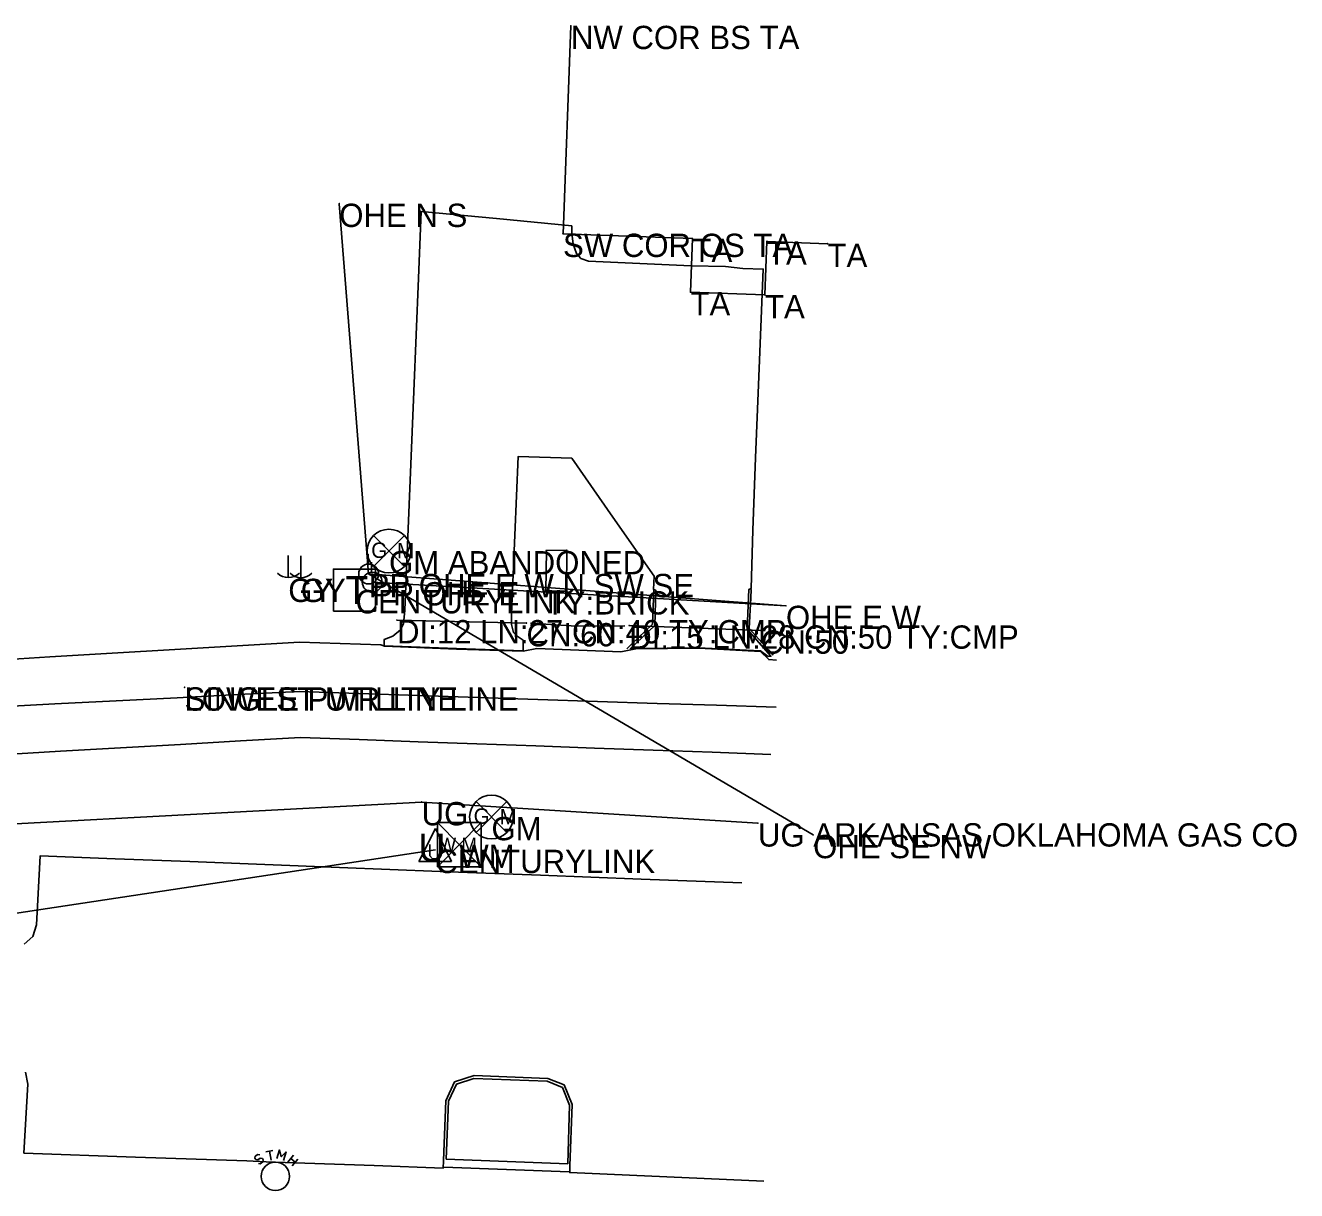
# Model space of a CAD drawing. Extents: x 675481 to 678499, y 212715 to 215285.
# Drawn here: x 678226 to 678498.8, y 214489.7 to 214739.6 of the extents above; entities that cross this region are included whole.
import ezdxf

# ---------------------------------------------------------------- set-up
doc = ezdxf.new("R2010")
doc.units = 0
for name, color, linetype in [('Default', 7, 'Continuous'), ('S_BUILDING', 7, 'Continuous'), ('S_BUILDING_ANNOT', 7, 'Continuous'), ('S_CURB', 7, 'Continuous'), ('S_DITCHLINE', 7, 'Continuous'), ('S_DRG_PT_SYM', 7, 'Continuous'), ('S_EDGE_CONCRETE', 7, 'Continuous'), ('S_EDGE_PAVEMENT', 7, 'Continuous'), ('S_ELECTRIC_UTILITIES', 7, 'Continuous'), ('S_ELECTRIC_UTILITIES_ANNOT', 7, 'Continuous'), ('S_GAS_UTILITIES', 7, 'Continuous'), ('S_GAS_UTILITIES_ANNOT', 7, 'Continuous'), ('S_MSC_PT_SYM', 7, 'Continuous'), ('S_PAVEMENT_CROWN', 7, 'Continuous'), ('S_SIDE_DRAIN', 7, 'Continuous'), ('S_SIDE_DRAIN_ANNOT', 7, 'Continuous'), ('S_SIGN', 7, 'Continuous'), ('S_SIGN_ANNOT', 7, 'Continuous'), ('S_STORM_SEWER', 7, 'Continuous'), ('S_STR_PT_SYM', 7, 'Continuous'), ('S_SURVEY_TEXT_ANNOT', 7, 'Continuous'), ('S_TELEPHONE_UTILITIES', 7, 'Continuous'), ('S_TELEPHONE_UTILITIES_ANNOT', 7, 'Continuous'), ('S_UNDERGROUND_CABLE', 7, 'Continuous'), ('S_UNDERGROUND_CABLE_ANNOT', 7, 'Continuous'), ('S_UTILITY_POLE', 7, 'Continuous'), ('S_UTILITY_POLE_ANNOT', 7, 'Continuous'), ('S_UTL_PT_SYM', 7, 'Continuous'), ('S_WATER_UTILITIES', 7, 'Continuous'), ('S_WATER_UTILITIES_ANNOT', 7, 'Continuous')]:
    doc.layers.add(name, color=color, linetype=linetype)

msp = doc.modelspace()

# ---------------------------------------------------------------- linework, layer by layer
at = {"layer": 'S_BUILDING'}
for p, q in [((678341.33, 214694.94), (678343.02, 214739.54)), ((678341.33, 214694.94), (678369.11, 214693.89)), ((678369.11, 214693.89), (678368.68, 214682.4)), ((678384.67, 214681.79), (678385.1, 214693.29)), ((678385.1, 214693.29), (678398.09, 214692.79)), ((678368.68, 214682.4), (678384.67, 214681.79))]:
    msp.add_line(p, q, dxfattribs=at)
at = {"layer": 'S_CURB'}
for points in [[(678360.8, 214618.48), (678360.76, 214616.66), (678360.54, 214611.15), (678355.96, 214606.79), (678355, 214605.85)], [(678386.45, 214604.54), (678385.42, 214605.68), (678381.3, 214610.21), (678381.6, 214616.83), (678381.71, 214618.6)], [(678342.35, 214495.43), (678329.31, 214495.92), (678316.26, 214496.41), (678316.76, 214508.83), (678318.49, 214512.5), (678322.22, 214513.73), (678337.92, 214513.14), (678341.2, 214511.79), (678342.75, 214507.99)], [(678342.75, 214507.99), (678342.35, 214495.43)], [(678315.73, 214494.67), (678329.2, 214494.18), (678342.67, 214493.7)]]:
    msp.add_lwpolyline(points, dxfattribs=at)
at = {"layer": 'S_DITCHLINE'}
msp.add_lwpolyline([(678334.34, 214611.4), (678344.14, 214610.75), (678354.6, 214610.78)], dxfattribs=at)
at = {"layer": 'S_DRG_PT_SYM'}
for points in [[(678305.7, 214612.05), (678305.7, 214612.1), (678305.7, 214612.05), (678305.65, 214612.05), (678305.7, 214612.05), (678305.7, 214612), (678305.7, 214612.05), (678305.75, 214612.05)], [(678333.49, 214611.41), (678333.49, 214611.46), (678333.49, 214611.41), (678333.44, 214611.41), (678333.49, 214611.41), (678333.49, 214611.36), (678333.49, 214611.41), (678333.54, 214611.41)], [(678355.53, 214610.9), (678355.53, 214610.95), (678355.53, 214610.9), (678355.48, 214610.9), (678355.53, 214610.9), (678355.53, 214610.85), (678355.53, 214610.9), (678355.58, 214610.9)], [(678383.79, 214609.83), (678383.79, 214609.88), (678383.79, 214609.83), (678383.74, 214609.83), (678383.79, 214609.83), (678383.79, 214609.78), (678383.79, 214609.83), (678383.84, 214609.83)]]:
    msp.add_lwpolyline(points, dxfattribs=at)
at = {"layer": 'S_EDGE_CONCRETE'}
msp.add_lwpolyline([(678343.23, 214696.62), (678327.07, 214698.17), (678310.92, 214699.72), (678310.3, 214685.41), (678309.29, 214661.12), (678308.28, 214636.82), (678307.39, 214614.2), (678307.07, 214611.26), (678306.48, 214609.96), (678304.81, 214608.63), (678302.92, 214607.87), (678302.98, 214606.49), (678318.48, 214605.92), (678332.78, 214605.48), (678332.76, 214607.75), (678331.68, 214608.45), (678330.73, 214609.39), (678330.28, 214611.08), (678330.24, 214613.4), (678330.98, 214630.28), (678331.71, 214647.17), (678343.21, 214646.78), (678352.04, 214634.11), (678360.88, 214621.44), (678360.78, 214618.6), (678361.22, 214618.43), (678361.03, 214610.91), (678355.78, 214605.98), (678357, 214605.96), (678370.36, 214606.1), (678383.72, 214605.42), (678385.34, 214604.2), (678385.93, 214604.29), (678380.82, 214610.07), (678381.22, 214618.64), (678381.69, 214618.8), (678382.07, 214631.31), (678382.66, 214646.89), (678383.25, 214662.48), (678384.3, 214687.33), (678379.94, 214687.49), (678376.21, 214687.92), (678368.86, 214688.05), (678346.78, 214689.03), (678345.16, 214689.65), (678344.22, 214690.72), (678343.49, 214692.72), (678343.22, 214695.03)], close=True, dxfattribs=at)
for points in [[(678293.37, 214558.97), (678277.31, 214559.6), (678261.25, 214560.23), (678245.18, 214560.86), (678229.12, 214561.5), (678228.32, 214546.69), (678227.52, 214544.13), (678225.69, 214542.52)], [(678379.69, 214555.66), (678358.11, 214556.49), (678336.53, 214557.31), (678314.95, 214558.14), (678293.37, 214558.97)], [(678225.95, 214515.05), (678226.45, 214512.47), (678225.63, 214497.7), (678249.55, 214496.86), (678273.48, 214496.02), (678277.6, 214495.85), (678281.7, 214495.69), (678285.95, 214495.55), (678300.78, 214495.02), (678315.61, 214494.49), (678315.66, 214496.05), (678315.69, 214496.12), (678316.19, 214508.89), (678318.05, 214512.96), (678322.25, 214514.31), (678338.05, 214513.67), (678341.56, 214512.33), (678343.3, 214508.15), (678342.8, 214494.96), (678342.76, 214493.53), (678363.59, 214492.61), (678384.43, 214491.69)]]:
    msp.add_lwpolyline(points, dxfattribs=at)
at = {"layer": 'S_EDGE_PAVEMENT'}
for points in [[(678217.78, 214603.34), (678231.18, 214604.14), (678244.59, 214604.94), (678257.99, 214605.74), (678271.39, 214606.54), (678284.8, 214607.34), (678302.25, 214606.76), (678303.01, 214606.45), (678318.46, 214605.83), (678332.79, 214605.4), (678335.72, 214605.96), (678353.71, 214605.2), (678356.98, 214605.9), (678370.52, 214606.01), (678383.68, 214605.33), (678385.49, 214603.58), (678387.12, 214603.48)], [(678220.63, 214583.15), (678233.5, 214583.9), (678246.37, 214584.64), (678259.25, 214585.38), (678272.12, 214586.12), (678285, 214586.86), (678297.61, 214586.41), (678310.23, 214585.95), (678322.85, 214585.5), (678335.47, 214585.04), (678348.08, 214584.59), (678360.7, 214584.13), (678373.32, 214583.68), (678385.94, 214583.23)]]:
    msp.add_lwpolyline(points, dxfattribs=at)
at = {"layer": 'S_ELECTRIC_UTILITIES'}
for p, q in [((678293.3, 214701.38), (678299.61, 214621.94)), ((678299.61, 214621.94), (678389.17, 214615.12)), ((678299.61, 214621.94), (678395, 214565.96)), ((678300.38, 214620.19), (678389.17, 214615.12))]:
    msp.add_line(p, q, dxfattribs=at)
at = {"layer": 'S_GAS_UTILITIES'}
for p, q in [((678300.67, 214623.54), (678307.29, 214630.16)), ((678300.67, 214630.16), (678307.29, 214623.54)), ((678310.98, 214573.01), (678187.31, 214566.36)), ((678383.16, 214568.46), (678310.98, 214573.01)), ((678322.66, 214566.5), (678329.28, 214573.12)), ((678322.66, 214573.12), (678329.28, 214566.5))]:
    msp.add_line(p, q, dxfattribs=at)
for centre in [(678303.98, 214626.85), (678325.97, 214569.81)]:
    msp.add_circle(centre, 4.68, dxfattribs=at)
at = {"layer": 'S_MSC_PT_SYM'}
for points in [[(678337.75, 214626.98), (678337.75, 214627.03), (678337.75, 214626.98), (678337.7, 214626.98), (678337.75, 214626.98), (678337.75, 214626.93), (678337.75, 214626.98), (678337.8, 214626.98)], [(678342.14, 214627.02), (678342.14, 214627.07), (678342.14, 214627.02), (678342.09, 214627.02), (678342.14, 214627.02), (678342.14, 214626.97), (678342.14, 214627.02), (678342.19, 214627.02)], [(678337.62, 214618.24), (678337.62, 214618.29), (678337.62, 214618.24), (678337.57, 214618.24), (678337.62, 214618.24), (678337.62, 214618.19), (678337.62, 214618.24), (678337.67, 214618.24)], [(678342.06, 214618.23), (678342.06, 214618.28), (678342.06, 214618.23), (678342.01, 214618.23), (678342.06, 214618.23), (678342.06, 214618.18), (678342.06, 214618.23), (678342.11, 214618.23)], [(678260.11, 214597.62), (678260.11, 214597.67), (678260.11, 214597.62), (678260.06, 214597.62), (678260.11, 214597.62), (678260.11, 214597.57), (678260.11, 214597.62), (678260.16, 214597.62)]]:
    msp.add_lwpolyline(points, dxfattribs=at)
at = {"layer": 'S_PAVEMENT_CROWN'}
msp.add_lwpolyline([(678219.2, 214593.4), (678232.3, 214594.07), (678245.4, 214594.74), (678258.5, 214595.4), (678271.6, 214596.07), (678284.7, 214596.73), (678297.5, 214596.31), (678310.3, 214595.88), (678323.1, 214595.46), (678335.9, 214595.03), (678348.7, 214594.61), (678361.5, 214594.18), (678374.3, 214593.76), (678387.1, 214593.33)], dxfattribs=at)
at = {"layer": 'S_SIDE_DRAIN'}
for p, q in [((678305.7, 214612.05), (678333.49, 214611.41)), ((678355.53, 214610.9), (678383.79, 214609.83))]:
    msp.add_line(p, q, dxfattribs=at)
at = {"layer": 'S_SIGN'}
for p, q in [((678337.62, 214618.24), (678337.75, 214626.98)), ((678337.75, 214626.98), (678342.14, 214627.02)), ((678342.14, 214627.02), (678342.06, 214618.23)), ((678342.06, 214618.23), (678337.62, 214618.24))]:
    msp.add_line(p, q, dxfattribs=at)
at = {"layer": 'S_STORM_SEWER'}
for p, q in [((678275.81, 214497.4), (678275.27, 214497.01)), ((678276.24, 214497.32), (678275.81, 214497.4)), ((678277.55, 214497.98), (678279.07, 214498.25)), ((678278.33, 214498.13), (678278.68, 214496.2)), ((678275.27, 214497.01), (678275.19, 214496.62)), ((678275.19, 214496.62), (678275.38, 214496.35)), ((678275.38, 214496.35), (678275.81, 214496.24)), ((678275.81, 214496.24), (678276.35, 214496.58)), ((678276.35, 214495.42), (678275.97, 214495.5)), ((678276.35, 214496.58), (678276.82, 214496.51)), ((678276.9, 214495.81), (678276.35, 214495.42)), ((678276.82, 214496.51), (678276.97, 214496.24)), ((678276.97, 214496.24), (678276.9, 214495.81)), ((678282.24, 214495.77), (678283.48, 214497.24)), ((678282.9, 214496.55), (678283.87, 214495.73)), ((678284.45, 214496.43), (678283.21, 214494.96))]:
    msp.add_line(p, q, dxfattribs=at)
msp.add_lwpolyline([(678281.35, 214496.08), (678281.89, 214497.94), (678280.85, 214496.93), (678280.46, 214498.37), (678279.92, 214496.51)], dxfattribs=at)
msp.add_circle((678279.6, 214492.71), 3.05, dxfattribs=at)
at = {"layer": 'S_STR_PT_SYM'}
for points in [[(678343.02, 214739.54), (678343.02, 214739.59), (678343.02, 214739.54), (678342.97, 214739.54), (678343.02, 214739.54), (678343.02, 214739.49), (678343.02, 214739.54), (678343.07, 214739.54)], [(678341.33, 214694.94), (678341.33, 214694.99), (678341.33, 214694.94), (678341.28, 214694.94), (678341.33, 214694.94), (678341.33, 214694.89), (678341.33, 214694.94), (678341.38, 214694.94)], [(678369.11, 214693.89), (678369.11, 214693.94), (678369.11, 214693.89), (678369.06, 214693.89), (678369.11, 214693.89), (678369.11, 214693.84), (678369.11, 214693.89), (678369.16, 214693.89)], [(678385.1, 214693.29), (678385.1, 214693.34), (678385.1, 214693.29), (678385.05, 214693.29), (678385.1, 214693.29), (678385.1, 214693.24), (678385.1, 214693.29), (678385.15, 214693.29)], [(678398.09, 214692.79), (678398.09, 214692.84), (678398.09, 214692.79), (678398.04, 214692.79), (678398.09, 214692.79), (678398.09, 214692.74), (678398.09, 214692.79), (678398.14, 214692.79)], [(678368.68, 214682.4), (678368.68, 214682.45), (678368.68, 214682.4), (678368.63, 214682.4), (678368.68, 214682.4), (678368.68, 214682.35), (678368.68, 214682.4), (678368.73, 214682.4)], [(678384.67, 214681.79), (678384.67, 214681.84), (678384.67, 214681.79), (678384.62, 214681.79), (678384.67, 214681.79), (678384.67, 214681.74), (678384.67, 214681.79), (678384.72, 214681.79)]]:
    msp.add_lwpolyline(points, dxfattribs=at)
at = {"layer": 'S_TELEPHONE_UTILITIES'}
msp.add_lwpolyline([(678292.07, 214613.98), (678292.07, 214622.98), (678301.07, 214622.98), (678301.07, 214613.98)], close=True, dxfattribs=at)
at = {"layer": 'S_UNDERGROUND_CABLE'}
for p, q in [((678313.93, 214567.31), (678310.41, 214560.22)), ((678313.93, 214567.31), (678317.42, 214560.22)), ((678312.73, 214561.46), (678312.73, 214563.9)), ((678315.1, 214563.9), (678315.1, 214561.46)), ((678313.93, 214562.77), (678000.75, 214515.3)), ((678310.41, 214560.22), (678317.42, 214560.22)), ((678313.35, 214560.8), (678312.73, 214561.46)), ((678314.55, 214560.8), (678313.35, 214560.8)), ((678315.1, 214561.46), (678314.55, 214560.8))]:
    msp.add_line(p, q, dxfattribs=at)
at = {"layer": 'S_UTILITY_POLE'}
for p, q in [((678282.34, 214625.87), (678282.34, 214621.15)), ((678285.03, 214625.85), (678285.03, 214621.13)), ((678299.49, 214624.09), (678299.49, 214626.19)), ((678300.26, 214622.33), (678300.26, 214624.44))]:
    msp.add_line(p, q, dxfattribs=at)
for centre in [(678299.61, 214621.94), (678300.38, 214620.19)]:
    msp.add_circle(centre, 2.13, dxfattribs=at)
for centre in [(678282.4, 214624.57), (678285.09, 214624.55)]:
    msp.add_arc(centre, 3.41, 226.3972, 313.6028, dxfattribs=at)
at = {"layer": 'S_UTL_PT_SYM'}
for points in [[(678293.3, 214701.38), (678293.3, 214701.43), (678293.3, 214701.38), (678293.25, 214701.38), (678293.3, 214701.38), (678293.3, 214701.33), (678293.3, 214701.38), (678293.35, 214701.38)], [(678299.61, 214621.94), (678299.61, 214621.99), (678299.61, 214621.94), (678299.56, 214621.94), (678299.61, 214621.94), (678299.61, 214621.9), (678299.61, 214621.94), (678299.66, 214621.94)], [(678299.61, 214621.94), (678299.61, 214621.99), (678299.61, 214621.94), (678299.56, 214621.94), (678299.61, 214621.94), (678299.61, 214621.9), (678299.61, 214621.94), (678299.66, 214621.94)], [(678299.61, 214621.94), (678299.61, 214621.99), (678299.61, 214621.94), (678299.56, 214621.94), (678299.61, 214621.94), (678299.61, 214621.9), (678299.61, 214621.94), (678299.66, 214621.94)], [(678299.61, 214621.94), (678299.61, 214621.99), (678299.61, 214621.94), (678299.56, 214621.94), (678299.61, 214621.94), (678299.61, 214621.9), (678299.61, 214621.94), (678299.66, 214621.94)], [(678300.38, 214620.19), (678300.38, 214620.24), (678300.38, 214620.19), (678300.33, 214620.19), (678300.38, 214620.19), (678300.38, 214620.14), (678300.38, 214620.19), (678300.43, 214620.19)], [(678389.17, 214615.12), (678389.17, 214615.17), (678389.17, 214615.12), (678389.12, 214615.12), (678389.17, 214615.12), (678389.17, 214615.07), (678389.17, 214615.12), (678389.22, 214615.12)], [(678389.17, 214615.12), (678389.17, 214615.17), (678389.17, 214615.12), (678389.12, 214615.12), (678389.17, 214615.12), (678389.17, 214615.07), (678389.17, 214615.12), (678389.22, 214615.12)], [(678260.11, 214597.62), (678260.11, 214597.67), (678260.11, 214597.62), (678260.06, 214597.62), (678260.11, 214597.62), (678260.11, 214597.57), (678260.11, 214597.62), (678260.16, 214597.62)], [(678310.98, 214573.01), (678310.98, 214573.06), (678310.98, 214573.01), (678310.93, 214573.01), (678310.98, 214573.01), (678310.98, 214572.96), (678310.98, 214573.01), (678311.03, 214573.01)], [(678383.16, 214568.46), (678383.16, 214568.51), (678383.16, 214568.46), (678383.11, 214568.46), (678383.16, 214568.46), (678383.16, 214568.41), (678383.16, 214568.46), (678383.21, 214568.46)], [(678395, 214565.96), (678395, 214566.01), (678395, 214565.96), (678394.95, 214565.96), (678395, 214565.96), (678395, 214565.91), (678395, 214565.96), (678395.05, 214565.96)]]:
    msp.add_lwpolyline(points, dxfattribs=at)
at = {"layer": 'S_WATER_UTILITIES'}
for p, q in [((678314.4, 214568.59), (678323.74, 214568.59)), ((678314.4, 214568.59), (678314.4, 214559.1)), ((678314.4, 214568.59), (678323.74, 214559.1)), ((678323.74, 214568.59), (678314.4, 214559.1)), ((678323.74, 214568.59), (678323.74, 214559.1)), ((678314.4, 214559.1), (678323.74, 214559.1))]:
    msp.add_line(p, q, dxfattribs=at)

# ---------------------------------------------------------------- texts
at = {"layer": 'Default'}
msp.add_text('U', height=6, rotation=360, dxfattribs=at).set_placement((678310.3, 214560.23))
at = {"layer": 'S_BUILDING_ANNOT'}
for s, p in [('NW COR BS TA', (678343.02, 214734.54)), ('SW COR OS TA', (678341.33, 214689.94)), ('TA', (678369.11, 214688.89)), ('TA', (678385.1, 214688.29)), ('TA ', (678398.09, 214687.79)), ('TA', (678368.68, 214677.4)), ('TA', (678384.67, 214676.79))]:
    msp.add_text(s, height=5, dxfattribs=at).set_placement(p)
at = {"layer": 'S_ELECTRIC_UTILITIES_ANNOT'}
for s, p in [('OHE N S', (678293.3, 214696.38)), ('PP OHE E W N SW SE', (678299.61, 214616.95)), ('PP OHE E W N SW SE', (678299.61, 214616.95)), ('PP OHE E W N SW SE', (678299.61, 214616.95)), ('PP OHE E W N SW SE', (678299.61, 214616.95)), ('PP OHE E', (678300.38, 214615.19)), ('OHE E W', (678389.17, 214610.12)), ('OHE E W', (678389.17, 214610.12)), ('LOWEST UTILITY LINE', (678260.11, 214592.62)), ('OHE SE NW', (678395, 214560.96))]:
    msp.add_text(s, height=5, dxfattribs=at).set_placement(p)
at = {"layer": 'S_GAS_UTILITIES'}
for s, p in [('G', (678300.16, 214625.38)), ('M', (678305.72, 214625.28)), ('G', (678322.15, 214568.35)), ('M', (678327.71, 214568.24))]:
    msp.add_text(s, height=3.3, rotation=360, dxfattribs=at).set_placement(p)
at = {"layer": 'S_GAS_UTILITIES_ANNOT'}
for s, p in [('GM ABANDONED', (678303.98, 214621.85)), ('UG', (678310.98, 214568.01)), ('GM', (678325.97, 214564.81)), ('UG ARKANSAS OKLAHOMA GAS CO', (678383.16, 214563.46))]:
    msp.add_text(s, height=5, dxfattribs=at).set_placement(p)
at = {"layer": 'S_SIDE_DRAIN_ANNOT'}
for s, p in [('DI:12 LN:27 CN:40 TY:CMP', (678305.7, 214607.05)), ('CN:60', (678333.49, 214606.41)), ('DI:15 LN:28 CN:50 TY:CMP', (678355.53, 214605.9)), ('CN:50', (678383.79, 214604.83))]:
    msp.add_text(s, height=5, dxfattribs=at).set_placement(p)
at = {"layer": 'S_SIGN_ANNOT'}
msp.add_text('TY:BRICK', height=5, dxfattribs=at).set_placement((678337.62, 214613.24))
at = {"layer": 'S_SURVEY_TEXT_ANNOT'}
msp.add_text('SINGLE PWR LINE', height=5, dxfattribs=at).set_placement((678260.11, 214592.62))
at = {"layer": 'S_TELEPHONE_UTILITIES'}
msp.add_text('T', height=6, rotation=360, dxfattribs=at).set_placement((678294.63, 214615.48))
at = {"layer": 'S_TELEPHONE_UTILITIES_ANNOT'}
msp.add_text('CENTURYLINK', height=5, dxfattribs=at).set_placement((678296.8, 214613.49))
at = {"layer": 'S_UNDERGROUND_CABLE_ANNOT'}
msp.add_text('CENTURYLINK', height=5, dxfattribs=at).set_placement((678313.93, 214557.77))
at = {"layer": 'S_UTILITY_POLE_ANNOT'}
for s, p in [('GY', (678282.36, 214615.93)), ('GY', (678285.04, 214615.91)), ('PP OHE E W N SW SE', (678299.61, 214616.95)), ('PP OHE E', (678300.38, 214615.19)), ('CENTURYLINK', (678313.93, 214557.77))]:
    msp.add_text(s, height=5, dxfattribs=at).set_placement(p)
at = {"layer": 'S_WATER_UTILITIES'}
msp.add_text('W M', height=3, rotation=360, dxfattribs=at).set_placement((678314.61, 214562.36))
at = {"layer": 'S_WATER_UTILITIES_ANNOT'}
msp.add_text('WM', height=5, dxfattribs=at).set_placement((678319.07, 214558.85))

doc.saveas('drawing.dxf')
